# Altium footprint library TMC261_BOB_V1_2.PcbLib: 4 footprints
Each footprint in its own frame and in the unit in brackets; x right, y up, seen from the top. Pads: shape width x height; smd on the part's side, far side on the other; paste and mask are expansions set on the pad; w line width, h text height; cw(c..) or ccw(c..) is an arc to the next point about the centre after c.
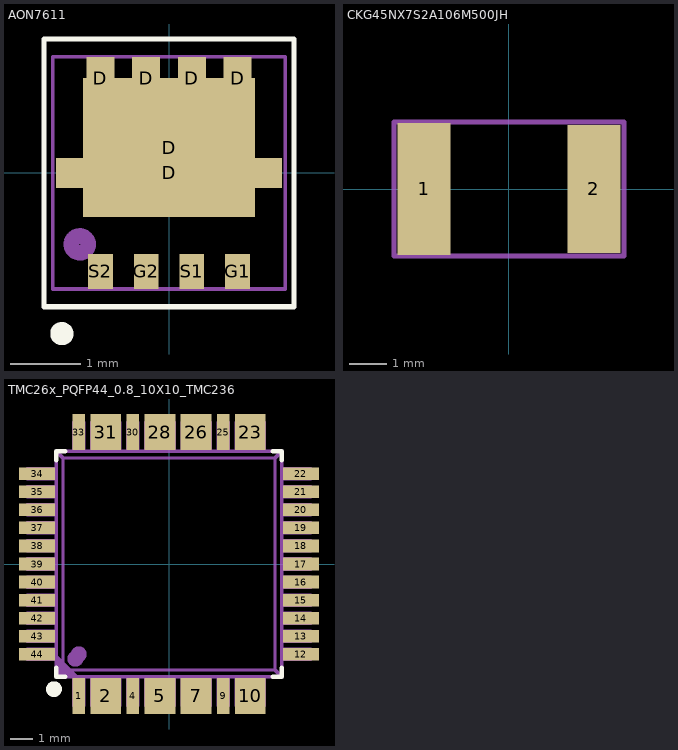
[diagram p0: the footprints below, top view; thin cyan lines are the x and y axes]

## AON7611 [mm]
pads (10):
  rect 0.4x0.6 smd: D(-0.975,1.35) D(-0.325,1.35) D(0.325,1.35) D(0.975,1.35)
  rect 3.21x0.43 smd: D(0,0)
  rect 2.45x1.98 smd: D(0,0.36)
  rect 0.35x0.5 smd: G1(0.975,-1.4) G2(-0.325,-1.4) S1(0.325,-1.4) S2(-0.975,-1.4)
Top Overlay:
  circle w0.178: c-1.524,-2.286 r0.076
  lines w0.076: -1.778,-1.905 1.778,-1.905 1.778,1.905 -1.778,1.905 -1.778,1.778 -1.778,-1.905
TopAsm:
  circle w0.22: c-1.27,-1.016 r0.12
  lines w0.051: -1.651,-1.651 -1.651,0 -1.651,1.651 0,1.651 1.651,1.651 1.651,0 1.651,-1.651 0,-1.651 -1.651,-1.651
  text ".Designator" at -1.27,-0.254 h0.51
3D body: height 0.9, standoff 0, extent -1.55,-1.55 1.55,1.55

## CKG45NX7S2A106M500JH [mm] "1812 STACKED capacitor"
pads (2):
  rect 1.4x3.5 smd: 1(-2.25,0)
  rect 1.4x3.4 smd: 2(2.25,0)
TopAsm:
  lines w0.14: -3.048,-1.778 3.048,-1.778 3.048,1.778 -3.048,1.778 -3.048,-1.778
  text ".Designator" at -2,-0.5 h1
3D body: height 0.25, standoff 0, extent 1.652,-1.6 2.412,1.6
3D body: height 0.25, standoff 0, extent -2.412,-1.6 -1.652,1.6
3D body: height 3.35, standoff 0, extent -2.5,-1.6 -2.25,1.6
3D body: height 3.35, standoff 0, extent 2.25,-1.6 2.5,1.6
3D body "User Library-SMD CAPACITOR(1).step": height 1.8, standoff 0.8, extent -2.25,-1.6 2.25,1.6
3D body "User Library-SMD CAPACITOR(1).step": height 3.3, standoff 2.3, extent -2.25,-1.6 2.25,1.6

## EMPTY_COMPONENT [mm]

## TMC26x_PQFP44_0.8_10X10_TMC236 [mm]
pads (36):
  rect 0.56x1.6 smd mask+0.044: 1(-4,-5.85) 4(-1.6,-5.85) 9(2.4,-5.85) 25(2.4,5.85) 30(-1.6,5.85) 33(-4,5.85)
  rect 1.36x1.6 smd mask+0.044: 2(-2.8,-5.85) 5(-0.4,-5.85) 7(1.2,-5.85) 10(3.6,-5.85) 23(3.6,5.85) 26(1.2,5.85) 28(-0.4,5.85) 31(-2.8,5.85)
  rect 1.6x0.56 smd mask+0.044: 12(5.85,-4) 13(5.85,-3.2) 14(5.85,-2.4) 15(5.85,-1.6) 16(5.85,-0.8) 17(5.85,0) 18(5.85,0.8) 19(5.85,1.6) 20(5.85,2.4) 21(5.85,3.2) 22(5.85,4) 34(-5.85,4) 35(-5.85,3.2) 36(-5.85,2.4) 37(-5.85,1.6) 38(-5.85,0.8) 39(-5.85,0) 40(-5.85,-0.8) 41(-5.85,-1.6) 42(-5.85,-2.4) 43(-5.85,-3.2) 44(-5.85,-4)
Top Overlay:
  circle w0.5: c-5.1,-5.55 r0.1
  lines w0.2: -5,-4.6 -5,-5 -4.6,-5 ; -5,4.6 -5,5 -4.6,5 ; 4.6,-5 5,-5 5,-4.6 ; 4.6,5 5,5 5,4.6
Mechanical 13:
  drawing of 189 lines, arcs and shapes, not listed
TopAsm:
  circle w0.5: c-4,-4 r0.1
  region: -5,-4 -4,-5 -5,-5
  lines w0.076: -5,-5 -5,5 5,5 5,-5 -5,-5
  text ".Designator" at -4,-0.5 h1.27
3D body: height 1.6, standoff 0, extent -5,-5 5,5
